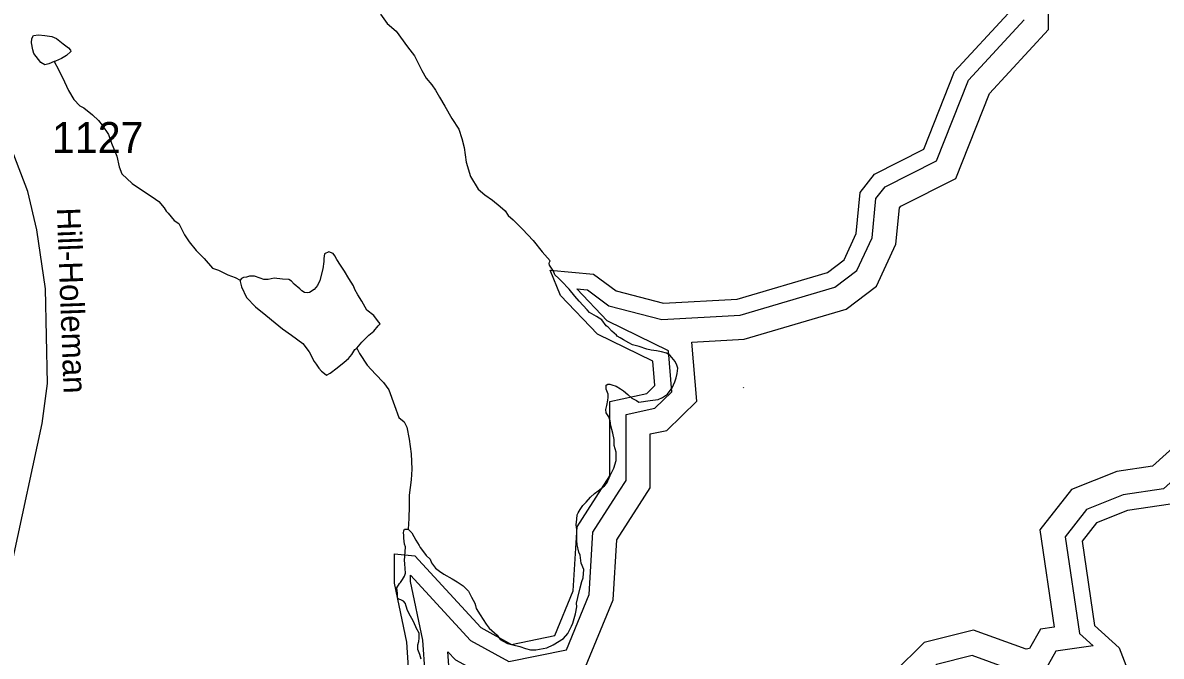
# Model space of a CAD drawing. Extents: x 2001466 to 2224147, y 644118 to 847247.
# Drawn here: x 2024583 to 2029202, y 684007 to 686579 of the extents above; entities that cross this region are included whole.
import ezdxf

# ---------------------------------------------------------------- set-up
doc = ezdxf.new("R2010")
doc.units = 0
for name, color, linetype in [('Exist Hydrographic Buffer Line', 7, 'Continuous'), ('Exist Hydrographic Lake Shore', 7, 'Continuous'), ('Exist Hydrographic Misc Water Feature', 7, 'Continuous'), ('Exist Road Non-System Type 51', 7, 'Continuous'), ('Exist Road Secondary Type 51 Attributed', 7, 'Continuous'), ('Exist Road Secondary Type 51 Label', 7, 'Continuous'), ('Exist Road Secondary Type 51 Number Label', 7, 'Continuous')]:
    doc.layers.add(name, color=color, linetype=linetype)

msp = doc.modelspace()

# ---------------------------------------------------------------- linework, layer by layer
at = {"layer": 'Exist Hydrographic Buffer Line'}
for points in [[(2027085.7, 684623.5), (2027129.1, 684691.2), (2027129.1, 684909.3), (2027196.3, 684924.1), (2027317.7, 685042.8), (2027298.3, 685282.5), (2027510.1, 685294.5), (2027923.3, 685415.7), (2028046.6, 685509.7), (2028125.7, 685679.2), (2028139.8, 685826.7), (2028145.8, 685834.4), (2028368.6, 685946.8), (2028505.4, 686292.1), (2028745.1, 686551.9), (2028745.1, 686846.5), (2028744.6, 686847), (2028746.3, 686847.2), (2029026.1, 687000.7), (2029201, 687199), (2029231.5, 687377.4), (2029361.6, 687484), (2029422, 687769.9), (2029386.9, 687982)], [(2027002.9, 684676.7), (2027030.7, 684720), (2027030.7, 684988.4), (2027147.6, 685014.1), (2027215.9, 685080.9), (2027202.4, 685247.5), (2026954.4, 685368.3), (2026830.6, 685498.1), (2026873.8, 685494), (2026961.4, 685429.7), (2027175.5, 685374.2), (2027493.2, 685392.1), (2027878.1, 685505), (2027967.7, 685573.3), (2028029.3, 685705.4), (2028044.6, 685864.6), (2028081.8, 685912.3), (2028290.9, 686017.8), (2028420.6, 686345.4), (2028646.7, 686590.4)], [(2029825.2, 684981.5), (2029603.9, 684998.9), (2029306.6, 684904.6), (2029167.2, 684779.2), (2029021.9, 684757.6), (2028838.1, 684684.1), (2028709.6, 684519.6), (2028767.3, 684125.4)], [(2029960.7, 684777.3), (2029882.1, 684878.3), (2029615.3, 684899.3), (2029356.7, 684817.2), (2029210.9, 684686.2), (2029047.8, 684661.9), (2028899.3, 684602.6), (2028813.1, 684492.2), (2028870.6, 684098.9), (2028925.8, 684048.8)], [(2024481, 682585.7), (2024490.8, 682594.6), (2024698.5, 682646), (2024938.2, 682858.7), (2024961.1, 682910.6), (2025148, 682924.4), (2025287.1, 683023), (2025407.5, 683169.1), (2025589.3, 683246.6), (2026134.7, 683610.3), (2026224.6, 683801.5), (2026206.1, 684072.6), (2026156.7, 684311), (2026156.7, 684335.9), (2026400, 684070.9), (2026555.7, 683986), (2026788.6, 684033.6), (2026880.8, 684258.3), (2026896.4, 684510.9), (2027002.9, 684676.7)], [(2024538.3, 682504.9), (2024745.7, 682556.3), (2025019.6, 682799.4), (2025027.3, 682816.8), (2025182.5, 682828.3), (2025354.7, 682950.2), (2025468.2, 683087.9), (2025636.4, 683159.7), (2026212.2, 683543.6), (2026324.5, 683782.8), (2026308, 684025.5), (2026338.5, 683992.3), (2026540.2, 683882.4), (2026859.7, 683947.7), (2026978, 684235.9), (2026993.1, 684479.3), (2027085.7, 684623.5)], [(2028767.3, 684125.4), (2028712.8, 684117.5), (2028668, 684038), (2028653.9, 684035.2), (2028440.8, 684113.1), (2028240.4, 684062.5), (2028116.9, 683940.4), (2027983.5, 683698.2), (2027995.4, 683357.9), (2028029.3, 683290), (2027977, 683201.9), (2027977, 682962), (2027585.3, 683000.7), (2027492.4, 682954.8), (2027160.2, 682944.8), (2026997.4, 682846.6), (2026885.3, 682703.2), (2026888.1, 682457.2)], [(2028925.8, 684048.8), (2028774.7, 684027), (2028731.6, 683950.5), (2028646.1, 683933.2), (2028435.5, 684010.3), (2028290.5, 683973.6), (2028196.2, 683880.4), (2028082.8, 683674.5), (2028093, 683382.8), (2028141.4, 683286), (2028075.4, 683174.9), (2028075.4, 682968.7), (2028220.8, 682764), (2028220.8, 682763.9), (2028052.7, 682855.6), (2027603.7, 682900), (2027516.8, 682857.1), (2027188.9, 682847.2), (2027063.7, 682771.7), (2026984.1, 682669.8), (2026986.5, 682466.1)]]:
    msp.add_lwpolyline(points, dxfattribs=at)
at = {"layer": 'Exist Hydrographic Lake Shore'}
for points in [[(2026952.9, 684720.3), (2026965.1, 684739.3), (2026965.1, 685041.2), (2027115.2, 685074.2), (2027148, 685106.3), (2027140, 685204.9), (2026915, 685314.5), (2026765.1, 685471.7), (2026723.1, 685574.3), (2026898, 685557.6), (2026990.1, 685490.1), (2027182, 685440.3), (2027482, 685457.2), (2027848, 685564.6), (2027915.1, 685615.7), (2027965.1, 685722.9), (2027981.1, 685889.9), (2028039.1, 685964.3), (2028239.1, 686065.2), (2028364.1, 686380.9), (2028581.1, 686616)], [(2029908.9, 684737), (2029848.1, 684815.2), (2029622.9, 684832.9), (2029390, 684758.9), (2029240.1, 684624.2), (2029065, 684598.2), (2028940.1, 684548.2), (2028882.1, 684473.9), (2028932.1, 684131.7)], [(2024437.1, 682634.5), (2024459.1, 682654.3), (2024667, 682705.8), (2024884, 682898.3), (2024917, 682973.1), (2025124.9, 682988.5), (2025242, 683071.4), (2025367.1, 683223.1), (2025558, 683304.6), (2026083.1, 683654.8), (2026158, 683814), (2026141, 684063.7), (2026091.1, 684304.3), (2026091.1, 684422.4), (2026174, 684414.2), (2026441, 684123.3), (2026566, 684055.1), (2026741.1, 684090.9), (2026816, 684273.2), (2026832, 684532), (2026952.9, 684720.3)], [(2028932.1, 684131.7), (2029032, 684041), (2029099, 683865.8), (2029107, 683740.9)]]:
    msp.add_lwpolyline(points, dxfattribs=at)
at = {"layer": 'Exist Hydrographic Misc Water Feature'}
for points in [[(2026033.9, 686614.1), (2026061.8, 686576.2), (2026097.9, 686544.2), (2026143.8, 686480.3), (2026171.9, 686444.3), (2026202.1, 686384.3), (2026219.9, 686354.3), (2026242.1, 686326.3), (2026258, 686304.4), (2026274, 686276.4), (2026296, 686240.4), (2026324.1, 686190.4), (2026352.2, 686146.4), (2026364.1, 686108.4), (2026374.1, 686072.4), (2026382.1, 686012.5), (2026400.1, 685954.5), (2026430.3, 685902.6), (2026458.2, 685880.6), (2026488.3, 685858.5), (2026520.3, 685832.6), (2026540.2, 685814.6), (2026552.3, 685796.6), (2026572.2, 685778.6), (2026610.3, 685740.7), (2026654.4, 685694.7), (2026690.3, 685648.7), (2026722.3, 685612.7)], [(2024710.1, 686421.3), (2024688.2, 686411.3), (2024672.2, 686407.3), (2024656.2, 686417.3), (2024628.1, 686453.3), (2024624.2, 686469.3), (2024618, 686497.3), (2024620.1, 686515.2), (2024626, 686527.2), (2024646.1, 686529.3), (2024672.2, 686527.2), (2024700.1, 686523.3), (2024720.2, 686515.3), (2024746.2, 686493.3), (2024768.1, 686477.4), (2024776.1, 686467.4), (2024778.2, 686461.4), (2024760.1, 686445.4), (2024740, 686433.3), (2024716.1, 686423.3), (2024710.1, 686421.3)], [(2024710.1, 686421.3), (2024728.2, 686389.4), (2024752.3, 686339.4), (2024768.3, 686303.4), (2024790.3, 686267.4), (2024814.3, 686241.5), (2024830.3, 686233.5), (2024866.2, 686205.5), (2024890.3, 686181.5), (2024904.3, 686163.5), (2024930.3, 686125.5), (2024942.4, 686089.6), (2024964.4, 686037.6), (2024974.4, 685993.6), (2024984.5, 685965.6), (2025026.3, 685925.6), (2025068.5, 685897.6), (2025108.5, 685871.6), (2025134.6, 685853.7), (2025156.5, 685827.7), (2025164.5, 685813.7), (2025172.5, 685805.7), (2025196.5, 685775.7), (2025216.4, 685763.8), (2025238.5, 685717.7), (2025258.4, 685689.8), (2025286.5, 685653.8), (2025318.5, 685621.8), (2025352.5, 685581.9), (2025376.5, 685573.9), (2025414.7, 685555.9), (2025444.6, 685544), (2025464.7, 685534)], [(2025938.8, 685258.3), (2025944.7, 685266.3), (2025958.7, 685282.3), (2025962.6, 685286.3), (2025986.6, 685310.4), (2026006.7, 685326.4), (2026024.5, 685348.3), (2026032.5, 685356.3), (2026022.6, 685370.3), (2026006.7, 685390.3), (2025978.6, 685412.3), (2025958.7, 685448.3), (2025942.5, 685474.3), (2025930.6, 685496.3), (2025924.4, 685510.3), (2025906.4, 685540.2), (2025888.5, 685570.2), (2025872.5, 685594.2), (2025856.6, 685618.1), (2025848.6, 685632.1), (2025842.4, 685642.1), (2025824.6, 685648.1), (2025806.5, 685640.1), (2025804.5, 685622.1), (2025804.5, 685610.1), (2025800.6, 685580.2), (2025788.5, 685532.2), (2025778.6, 685512.1), (2025764.7, 685496.1), (2025746.6, 685484.1), (2025736.6, 685482.1), (2025726.6, 685484.1), (2025714.7, 685490.1), (2025706.7, 685498.1), (2025684.5, 685518.1), (2025672.6, 685530.1), (2025662.6, 685536.1), (2025636.5, 685538.1), (2025602.7, 685542), (2025578.5, 685536), (2025560.7, 685536), (2025546.5, 685542), (2025522.5, 685550), (2025502.6, 685550), (2025490.5, 685546), (2025478.6, 685544), (2025470.6, 685540), (2025464.7, 685534)], [(2027228.6, 685121.2), (2027234.5, 685137.1), (2027238.6, 685155.1), (2027240.5, 685177.1), (2027236.6, 685189.1), (2027230.4, 685203.1), (2027216.5, 685219.1), (2027208.5, 685229.1), (2027194.5, 685237.1), (2027174.4, 685243.1), (2027154.5, 685247.1), (2027132.4, 685249.1), (2027114.5, 685253), (2027084.4, 685265), (2027056.5, 685271), (2027042.4, 685279), (2027020.4, 685291), (2027006.5, 685299), (2026994.4, 685307), (2026992.5, 685311), (2026972.4, 685327), (2026958.5, 685342.9), (2026950.5, 685348.9), (2026932.5, 685372.9), (2026910.5, 685386.8), (2026892.5, 685396.9), (2026882.4, 685402.8), (2026872.4, 685412.8), (2026840.4, 685448.9), (2026822.6, 685468.9), (2026800.4, 685496.8), (2026790.4, 685506.8), (2026778.3, 685520.8), (2026758.4, 685540.8), (2026742.4, 685554.7), (2026736.4, 685570.7), (2026720.4, 685594.7), (2026718.4, 685600.7), (2026720.4, 685606.7), (2026722.3, 685612.7)], [(2025464.7, 685534), (2025464.7, 685528), (2025470.6, 685506), (2025490.5, 685463.9), (2025526.6, 685426), (2025568.7, 685392), (2025606.6, 685360), (2025636.7, 685336.1), (2025672.6, 685310.1), (2025718.8, 685276.2), (2025744.8, 685242.1), (2025764.7, 685204.2), (2025772.7, 685192.2), (2025784.8, 685176.2), (2025794.6, 685164.2), (2025806.7, 685154.2), (2025814.7, 685148.2), (2025830.7, 685156.2), (2025858.8, 685178.2), (2025886.7, 685200.3), (2025904.7, 685216.3), (2025918.7, 685232.3), (2025930.8, 685252.3), (2025938.8, 685258.3)], [(2025938.8, 685258.3), (2025948.6, 685236.3), (2025980.6, 685188.4), (2026014.6, 685152.4), (2026046.6, 685118.4), (2026068.8, 685088.4), (2026090.9, 685024.4), (2026108.8, 684976.5), (2026130.9, 684958.5), (2026140.8, 684936.4), (2026150.8, 684888.5), (2026159, 684828.5), (2026160.9, 684766.5), (2026159, 684722.5), (2026151, 684660.6), (2026151, 684616.5), (2026149.2, 684566.5), (2026147.1, 684522.6)], [(2026147.1, 684522.6), (2026161.1, 684508.6), (2026177.1, 684478.5), (2026191, 684456.6), (2026195.1, 684448.6), (2026209.2, 684430.6), (2026219.1, 684416.6), (2026235.3, 684400.6), (2026241.2, 684386.6), (2026257.2, 684364.6), (2026273.2, 684352.7), (2026291.3, 684340.7), (2026325.1, 684320.7), (2026345.2, 684308.7), (2026369.2, 684292.7), (2026391.1, 684270.7), (2026397.3, 684260.7), (2026403.2, 684246.7), (2026417.2, 684222.8), (2026419.2, 684212.7), (2026423.1, 684200.8), (2026439.1, 684174.8), (2026463.3, 684136.8), (2026475.4, 684120.8), (2026507.4, 684092.9), (2026519.3, 684074.9), (2026529.3, 684068.9), (2026549.2, 684058.9), (2026571.4, 684052.9), (2026599.3, 684046.9), (2026623.2, 684038.9), (2026643.3, 684032.9), (2026665.3, 684032.9), (2026709.4, 684041), (2026735.2, 684053), (2026777.2, 684079), (2026795.1, 684099), (2026809.2, 684129.1), (2026815.2, 684141), (2026825.2, 684179), (2026831.2, 684207), (2026829.1, 684223), (2026835.3, 684245), (2026845.1, 684285), (2026851.1, 684311), (2026857, 684325), (2026859.1, 684359), (2026849, 684385), (2026845.1, 684417), (2026839, 684429), (2026833, 684459), (2026831, 684477), (2026831, 684503), (2026831, 684521), (2026828.9, 684541), (2026831, 684563), (2026833, 684581), (2026836.9, 684589), (2026844.9, 684603), (2026855, 684619), (2026868.9, 684633), (2026886.9, 684653), (2026902.7, 684667), (2026916.9, 684679), (2026942.7, 684699), (2026952.8, 684709), (2026966.9, 684741), (2026980.9, 684771), (2026990.9, 684801.1), (2026990.9, 684835.1), (2026982.7, 684863), (2026982.7, 684887), (2026976.8, 684913), (2026968.8, 684943), (2026966.7, 684963), (2026960.8, 684979), (2026950.7, 684995), (2026948.7, 685009), (2026952.8, 685025), (2026956.7, 685047), (2026958.7, 685057), (2026958.7, 685071), (2026950.5, 685091), (2026950.5, 685106.9), (2026956.7, 685111), (2026964.7, 685111), (2026972.7, 685109), (2026990.5, 685103), (2027008.5, 685093), (2027020.6, 685085.1), (2027038.5, 685069.1), (2027054.7, 685055.1), (2027072.5, 685045.1), (2027082.6, 685039.1), (2027128.5, 685045.1), (2027160.5, 685049.1), (2027178.5, 685057.1), (2027198.6, 685071.1), (2027218.5, 685097.1), (2027228.6, 685121.2)], [(2026129.1, 684486.5), (2026129.1, 684498.5), (2026127, 684508.6), (2026129.1, 684516.6), (2026131.1, 684522.6), (2026147.1, 684522.6)], [(2026199.4, 683994.6), (2026193.5, 684014.6), (2026185.3, 684034.6), (2026185.3, 684052.7), (2026189.4, 684066.6), (2026191.2, 684080.7), (2026191.4, 684100.6), (2026179.3, 684122.6), (2026177.3, 684126.6), (2026167.2, 684150.6), (2026151.2, 684178.6), (2026143.2, 684196.6), (2026139.3, 684206.5), (2026137.3, 684214.6), (2026135.2, 684220.5), (2026127.2, 684230.6), (2026117.4, 684236.6), (2026109.4, 684238.6), (2026103.2, 684244.6), (2026103.2, 684252.5), (2026103.2, 684262.5), (2026101.2, 684284.5), (2026111.2, 684302.5), (2026115.1, 684306.5), (2026123.1, 684318.5), (2026131.1, 684332.5), (2026135.2, 684344.5), (2026133.2, 684382.6), (2026131.1, 684396.5), (2026133.2, 684412.5), (2026135.2, 684450.5), (2026131.1, 684462.5), (2026129.1, 684486.5)]]:
    msp.add_lwpolyline(points, dxfattribs=at)
at = {"layer": 'Exist Road Non-System Type 51'}
msp.add_line((2027507.3, 685097), (2027508.8, 685098.9), dxfattribs=at)
at = {"layer": 'Exist Road Secondary Type 51 Attributed'}
msp.add_lwpolyline([(2024544.3, 684404.7), (2024661.4, 684951.9), (2024682.6, 685114.6), (2024675.2, 685499.1), (2024639.3, 685737.8), (2024603.4, 685894.2), (2024435.5, 686329.4)], dxfattribs=at)

# ---------------------------------------------------------------- texts
at = {"layer": 'Exist Road Secondary Type 51 Label'}
msp.add_text('Hill-Holleman', height=95, rotation=272.1074, dxfattribs=at).set_placement((2024721, 685826.9))
at = {"layer": 'Exist Road Secondary Type 51 Number Label'}
msp.add_text('1127', height=125, dxfattribs=at).set_placement((2024700.9, 686050.5))

doc.saveas('drawing.dxf')
